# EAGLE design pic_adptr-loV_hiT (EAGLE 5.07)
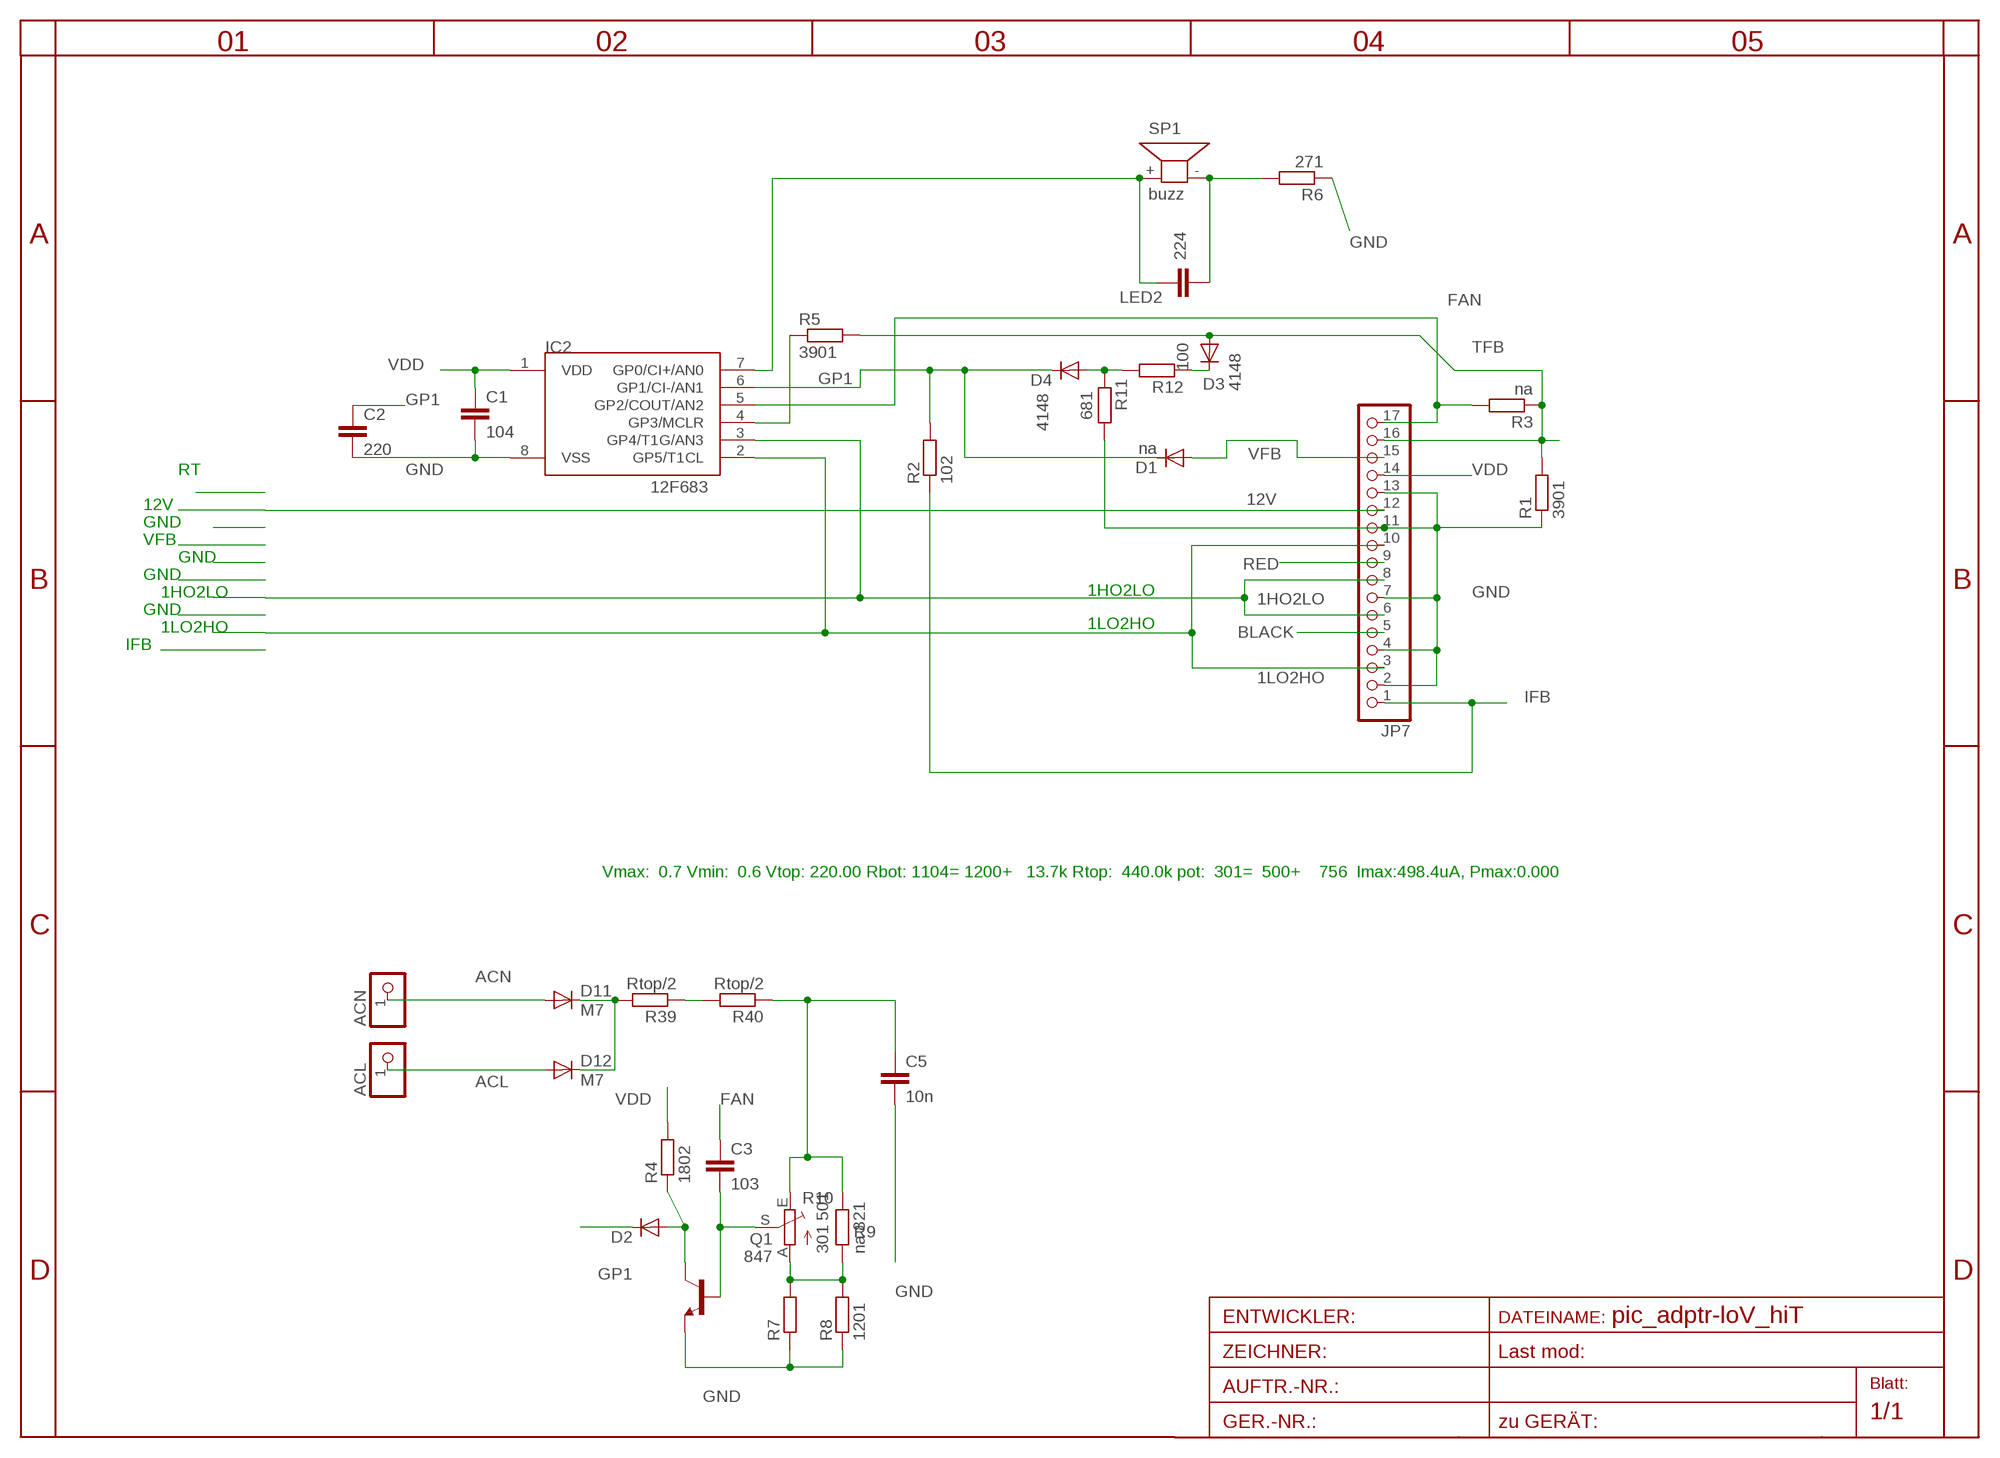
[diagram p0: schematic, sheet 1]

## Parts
ACL  PINHD-1X11X0.4  [1X01]
ACN  PINHD-1X11X0.4  [1X01]
C1  104  C-EUC1206  [C1206]
C2  220  C-EUC0805  [C0805]
C3  103  C-EUC0805  [C0805]
C5  10n  C-EUC0805  [C0805]
D1  na  DIODE-MINIMELF  [MINIMELF]
D2  DIODE-MINIMELF  [MINIMELF]
D3  4148  DIODE-MINIMELF  [MINIMELF]
D4  4148  DIODE-MINIMELF  [MINIMELF]
D11  M7  DIODE-SMA-DO214  [SMA-DO214AC]
D12  M7  DIODE-SMA-DO214  [SMA-DO214AC]
IC2  12F683  PIC12F675P  [DIL8]
JP7  PINHD-1X17  [1X17]
LED2  224  C-EUC1206K  [C1206K]
Q1  847  BC847ALT1SMD  [SOT23]
R1  3901  R-EU_R0805  [R0805]
R2  102  R-EU_R0805  [R0805]
R3  na  R-EU_R0805  [R0805]
R4  1802  R-EU_R1206  [R1206]
R5  3901  R-EU_R0805  [R0805]
R6  271  R-EU_R0805  [R0805]
R7  R-EU_R0805  [R0805]
R8  1201  R-EU_R0805  [R0805]
R9  na 821  R-EU_R1206  [R1206]
R10  301 501  TRIM_EU-B64Y  [B64Y]
R11  681  R-EU_R0805  [R0805]
R12  100  R-EU_R0805  [R0805]
R39  Rtop/2  R-EU_R1206  [R1206]
R40  Rtop/2  R-EU_R1206  [R1206]
SP1  buzz  KSS12017MM  [KSS1202]

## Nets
1HO2LO: IC2.3(GP4/T1G/AN3) JP7.6 JP7.8
1LO2HO: IC2.2(GP5/T1CL) JP7.3 JP7.10
12V: JP7.12
ACL: ACL.1 D12.A
ACN: ACN.1 D11.A
BLACK: JP7.5
FAN: C3.1 IC2.5(GP2/COUT/AN2) JP7.17 R3.2
GND: C1.2 C2.2 C5.2 IC2.8(VSS) JP7.2 JP7.4 JP7.7 JP7.11 JP7.13 Q1.2(E) R1.1 R6.1 R7.1 R8.1 R11.2
GP1: C2.1 D1.C D2.C D4.C IC2.6(GP1/CI-/AN1) R2.2
IFB: JP7.1 R2.1
N$2: D11.K(C) D12.K(C) R39.2
N$3: IC2.4(GP3/MCLR) R5.1
N$4: IC2.7(GP0/CI+/AN0) LED2.1 SP1.+
N$5: LED2.2 R6.2 SP1.-
N$6: R39.1 R40.2
N$7: D2.A Q1.3(C) R4.1
N$8: D3.C R12.1
N$9: D4.A R11.1 R12.2
N$12: R7.2 R8.2 R9.1 R10.A
N$13: C3.2 Q1.1(B) R10.S
N$19: C5.1 R9.2 R10.E R40.1
RED: JP7.9
TFB: D3.A JP7.16 R1.2 R3.1 R5.2
VDD: C1.1 IC2.1(VDD) JP7.14 R4.2
VFB: D1.A JP7.15

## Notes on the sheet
- Vmax:  0.7 Vmin:  0.6 Vtop: 220.00 Rbot: 1104= 1200+   13.7k Rtop:  440.0k pot:  301=  500+    756  Imax:498.4uA, Pmax:0.000

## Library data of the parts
ACL ACN = pinhead:PINHD-1X1: PIN HEADER
C1-C3 C5 = rcl:C-EU: CAPACITOR, European symbol
D1-D4 D11 D12 = diode:DIODE-: DIODE
IC2 = microchip-5:PIC12F6*: uPC nW 1k Program Flash memory 2x Timer Comparator 10b A/D converter/ 4xIN
JP7 = pinhead:PINHD-1X17: PIN HEADER
LED2 = rcl-2:C-EU: CAPACITOR, European symbol
Q1 = transistor-npn:BC847*: NPN Transistor
R1-R9 R11 R12 = rcl:R-EU_: RESISTOR, European symbol
R10 = pot:TRIM_EU-: POTENTIOMETER
R39 R40 = rcl-2:R-EU_: RESISTOR, European symbol
SP1 = buzzer:KSS1201: SPEAKER

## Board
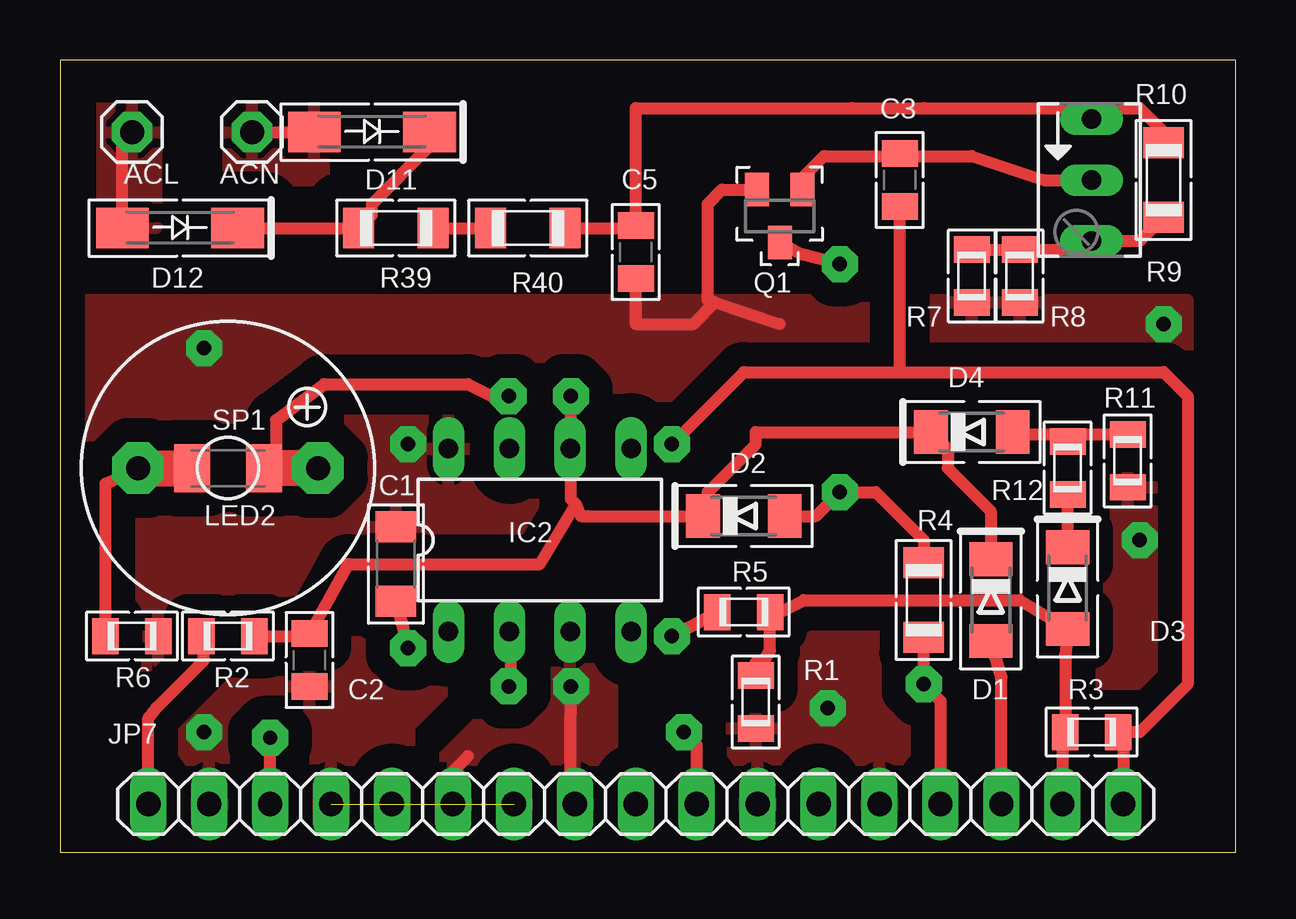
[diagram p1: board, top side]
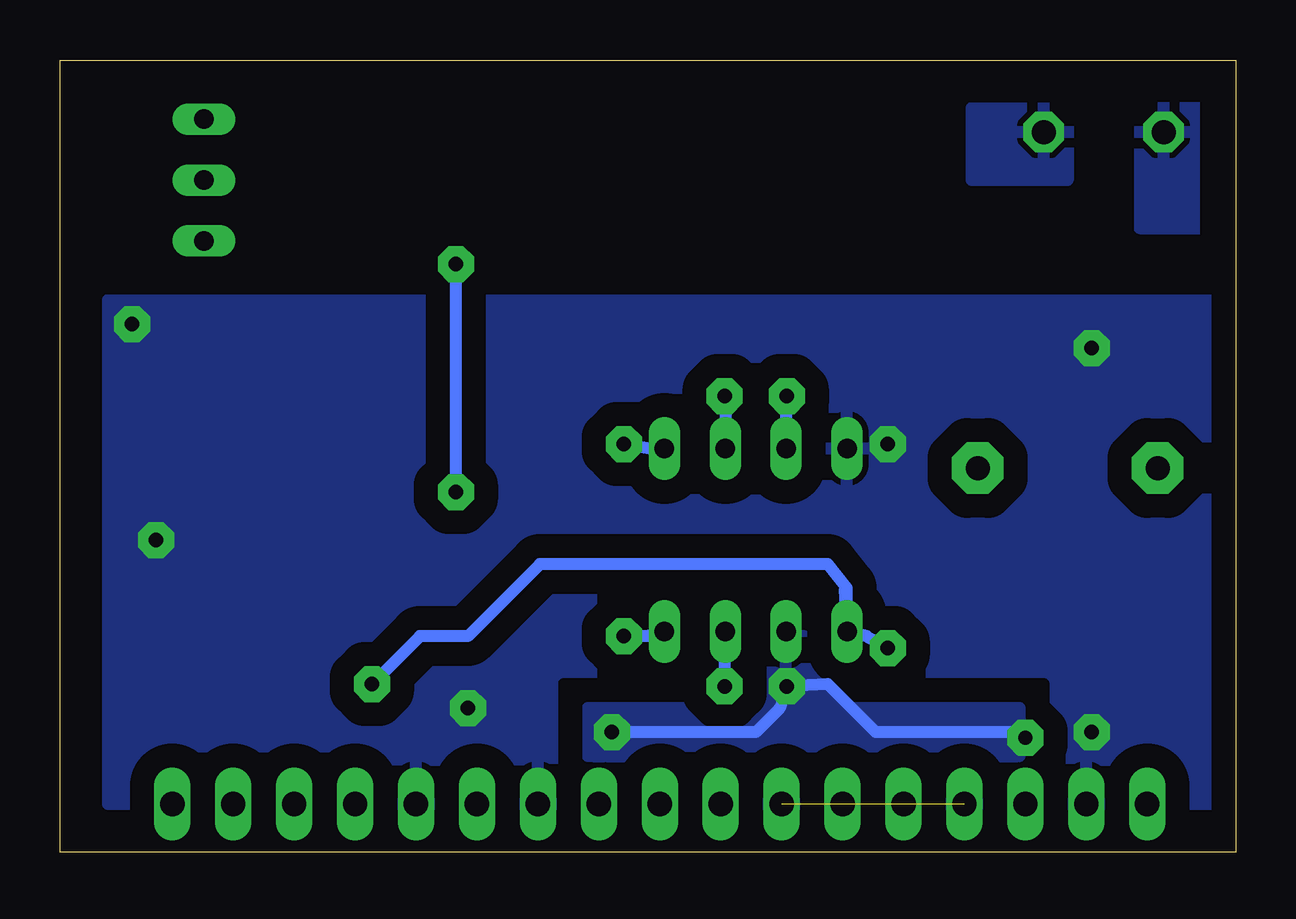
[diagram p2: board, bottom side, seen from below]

Size 49 x 33 mm. Coordinates in mm from the lower left corner, seen from the top.
Outline: 0,0 49,0 49,33 0,33 0,0
Copper layers (1*16): Top 0.035mm / dielectric 1.5mm / Bottom 0.035mm
Design rules "default *": minimum track width 10mil, minimum drill 20mil, track to track 8mil, track to pad 8mil, pad to pad 8mil, via to via 8mil, smd to smd 8mil, copper to edge 40mil, drill to drill 8mil, minimum pad ring 10mil, minimum via ring 8mil, stop-mask expansion 4mil, vias tented up to drill 0mil, thermal gap 10mil

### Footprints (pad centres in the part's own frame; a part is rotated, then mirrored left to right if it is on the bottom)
1X01 = drill 1 pad 1.676 octagon: 1 0,0
C1206 = smd 1.3 x 1.7: 1 -1.55,0; 2 1.55,0
C0805 = smd 1.1 x 1.5: 1 -1.1,0; 2 1.1,0
MINIMELF = smd 1.4 x 1.8: A 1.7,0; C -1.7,0
SMA-DO214AC = smd 2.2 x 1.7: A 2.4,0; K -2.4,0
DIL8 = drill 0.8 long: 1 -3.81,-3.81; 2 -1.27,-3.81; 3 1.27,-3.81; 4 3.81,-3.81; 5 3.81,3.81; 6 1.27,3.81; 7 -1.27,3.81; 8 -3.81,3.81
1X17 = drill 1.016 long: 1 -20.32,0; 2 -17.78,0; 3 -15.24,0; 4 -12.7,0; 5 -10.16,0; 6 -7.62,0; 7 -5.08,0; 8 -2.54,0; 9 0,0; 10 2.54,0; 11 5.08,0; 12 7.62,0; 13 10.16,0; 14 12.7,0; 15 15.24,0; 16 17.78,0; 17 20.32,0
C1206K = smd 1.5 x 2: 1 -1.5,0; 2 1.5,0
SOT23 = smd 1 x 1.4: 1 -0.95,-1.1; 2 0.95,-1.1; 3 0,1.1
R0805 = smd 1.1 x 1.5: 1 -1.1,0; 2 1.1,0
R1206 = smd 1.3 x 1.7: 1 -1.55,0; 2 1.55,0
B64Y = drill 0.813 long: A 2.54,0; E -2.54,0; S 0,0
KSS1202 = drill 1 pad 2.159 octagon: + 3.75,0; - -3.75,0

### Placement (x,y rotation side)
ACL  3,30 0 top
ACN  8,30 0 top
C1  14,12 90 top
C2  10.4,8 270 top
C3  35,28 90 top
C5  24,25 270 top
D1  38.8,10.5 270 top
D2  28.5,14 0 top
D3  42,11 270 top
D4  38,17.5 0 top
D11  13,30 180 top
D12  5,26 180 top
IC2  20,13 0 top
JP7  24,2 0 top
LED2  7,16 180 top
Q1  30,26.5 180 top
R1  29,6.25 90 top
R2  7,9 0 top
R3  43,5 0 top
R4  36,10.5 270 top
R5  28.5,10 0 top
R6  3,9 180 top
R7  38,24 90 top
R8  40,24 90 top
R9  46,28 90 top
R10  43,28 270 top
R11  44.5,16.3 270 top
R12  42,16 90 top
R39  14,26 180 top
R40  19.5,26 180 top
SP1  7,16 0 top

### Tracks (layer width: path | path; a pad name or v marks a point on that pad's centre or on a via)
1HO2LO  (via drill 0.6 pad 1.5)
  Top 0.5: v21.3,6.9 21.27,2.19 JP7.8 | 17,4 16,3 16,2.38 JP7.6
  Bottom 0.5: v21.3,6.9 IC2.3
  pour Top (isolate 1, rank 2): 20,8 23,8 23,1 21,1 21,3 18,3 18,2 17,1 15,1 15,3
1LO2HO  (via drill 0.6 pad 1.5)
  Top 0.5: JP7.3 v8.76,4.76 | JP7.10 26.54,4.46 v26,5 | v18.7,6.9 18.8,7.6 18.8,9.1
  Bottom 0.5: v8.76,4.76 9,5 15,5 16,6 17,7 v18.7,6.9 19,6 20,5 v26,5 | IC2.2 19,8.92 IC2.2
  pour Bottom (isolate 1): 19,9 20,8 20,7 21,6 27,6 27,4 9,4 9,6 16,6 17,7 17,8 18,9
ACL
  Top 0.5: D12.A 2.6,29.4 ACL.1
  pour Bottom (isolate 1.5): 1,31 4,31 4,26 1,26
  pour Top (isolate 1.5): 1,31 4,31 4,26 1,26
ACN
  Top 0.5: ACN.1 D11.A
  pour Bottom (isolate 1.5): 7,31 7,28 11,28 11,31
  pour Top (isolate 1.5): 7,31 7,28 11,28 11,31
FAN  (via drill 0.6 pad 1.5)
  Top 0.5: JP7.17 44.32,4.78 R3.2 45,5 47,7 47,19 46,20 35,20 | 35,20 28.5,20 v25.5,17 | 35,20 C3.1
  Bottom 0.5: IC2.5 24.41,16.81 v25.5,17
GND  (via drill 0.6 pad 1.5)  (1 unrouted)
  Top 0.5: 27.3,22.9 27,23 27,27 27.6,27.6 Q1.2 | 27.3,22.9 30,22 | C5.2 24,22 26.4,22 27.3,22.9
  other vias: 46,22 14.5,17 6,21 45,13 32,6 6,5
  pour Top (isolate 1, rank 3): 47,23 1,23 1,1 47,1
  pour Bottom (isolate 1, rank 3): 47,23 1,23 1,2 47,2
GP1  (via drill 0.6 pad 1.5)
  Top 0.5: 21.5,14.5 21.7,14 22,14 27,14 | 21.5,14.5 20,12 12,12 C2.1 10.3,9 R2.2 | v21.3,19 21.3,16.3 21.3,14.7 21.5,14.5 | 27,14 D2.C 27,14 | 39.2,12.2 39,12 D1.C 38.8,14.2 38,15 37,16 37,16.8 D4.C 36,17.5 29,17.5 29,17 27,15 27,14
  Bottom 0.5: IC2.6 21.27,18.77 v21.3,19
IFB
  Top 0.5: JP7.1 3.68,5.58 4,6 6,8 R2.1
N$2
  Top 0.5: D11.K 15.4,29.4 13,27 13,26.55 R39.2 D12.K
N$3  (via drill 0.6 pad 1.5)
  Top 0.5: v25.5,9 R5.1
  Bottom 0.5: v25.5,9 24.52,9 IC2.4
N$4  (via drill 0.6 pad 1.5)
  Top 0.5: v18.7,19 18.2,18.8 18,19 17,19.5 11,19.5 9,18 9,16.25 9,16 | LED2.1 9,16 | 9,16 10,16
  Top 1.5: 9,16 10,16 SP1.+
  Bottom 0.5: IC2.7 18.73,18.77 v18.7,19
N$5
  Top 0.5: R6.2 1.9,15.35 SP1.-
  Top 1.5: SP1.- LED2.2
N$6
  Top 0.5: R39.1 17.45,26 R40.2
N$7  (via drill 0.6 pad 1.5)
  Top 0.5: Q1.3 30.9,24.9 v32.5,24.5 | D2.A 31.5,14 v32.5,15 34,15 36,13 R4.1
  Bottom 0.5: v32.5,15 v32.5,24.5
N$8
  Top 0.5: D3.C 42,12.9 R12.1
N$9
  Top 0.5: R11.1 42.1,17.4 42.02,17.4 | R12.2 42,17.39 42.02,17.4 | 42.02,17.4 39.8,17.4 D4.A
N$12
  Top 0.5: R7.2 R8.2 42.64,25.1 R10.A 45.01,25.46 R9.1
N$13
  Top 0.5: R10.S 41,28 38,29 34,29 | 34,29 31.85,29 30.95,28.1 Q1.1 | 34,29 34.9,29 C3.2
N$19
  Top 0.5: C5.1 23.95,26.5 | C5.1 24,28 24,31 33,31 36,31 42.54,31 R10.E 43.46,31 45,31 46,30 R9.2 | R40.1 23.9,26 C5.1
TFB
  Top 0.5: JP7.16 41.78,4.88 R3.1 41.9,8.2 D3.A 40,10.5 31,10.5 30,10 R5.2 29.6,8.4 R1.2 29,7.9
VDD  (via drill 0.6 pad 1.5)
  Top 0.5: C1.1 v14.5,8.5 | JP7.14 36.7,6.3 v36,7 R4.2
  Bottom 0.5: IC2.1 16.2,9.48 16.2,11 17,12 29,12 32,9 34,9 v36,7 35.7,7 | IC2.1 16.28,11 | v14.5,8.5 15.38,9 IC2.1
VFB
  Top 0.5: JP7.15 39.24,7.29 D1.A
